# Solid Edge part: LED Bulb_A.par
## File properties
Title: Bulb
Author: NMH
Template: iso metric part.par
Last saved by: NMH
Revision: 2
Application: Solid Edge
Accuracy: 0.990
Rev B: B
Rev B Text: -
Rev B Date: -
Rev C: C
Rev C Text: -
Rev C Date: -
Rev D: D
Rev D Text: -
Rev D Date: -
Part Number: -
Profile: -
Casting: -
Username: NMH
Document Number: B
Revision: A
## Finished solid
Body 1: solid body, 6 faces, 9 edges, 5 vertices.
  Faces by surface: plane 3, cone 1, cylinder 1, sphere 1
  Edges by curve: line 5, circle 4
Bounding box of the edges (mm; curved faces can reach further): 5.310 x 5.860 x 6.813, from (-2.93, -2.93, 0) to (2.38, 2.93, 6.8131).
Cylindrical faces by radius (mm): R2.93 x1
Conical faces (half-angle, radius in mm at the cone's reference point): 0.8313 deg R2.3 x1
Spherical faces by radius (mm): R2.3002 x1
Planar faces by outward normal: +x 1, +z 1, -z 1
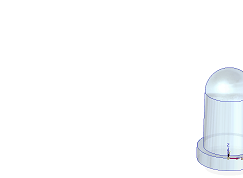
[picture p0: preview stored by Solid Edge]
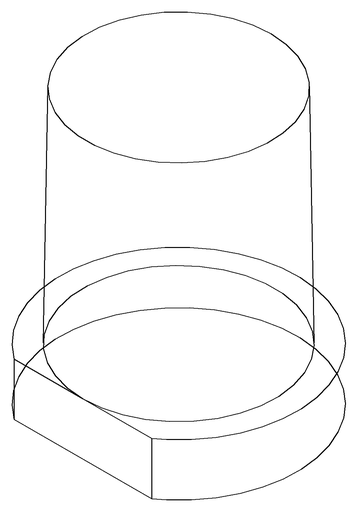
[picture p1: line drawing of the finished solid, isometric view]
